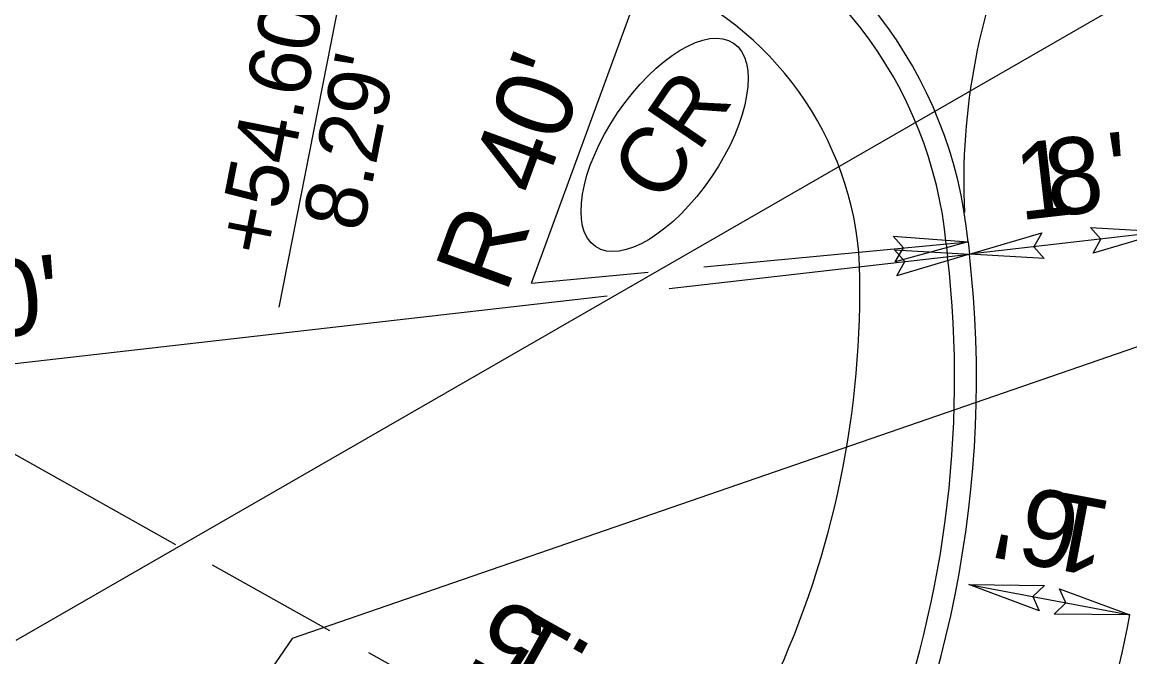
# Model space of a CAD drawing. Extents: x 1975573 to 1977432, y 778300 to 780514.
# Drawn here: x 1976181.7 to 1976308, y 779399.7 to 779472 of the extents above; entities that cross this region are included whole.
import ezdxf

# ---------------------------------------------------------------- set-up
doc = ezdxf.new("R2010")
doc.units = 0
for name, color, linetype in [('Prop Conc 2ft 6in Curb and Gutter', 7, 'Continuous'), ('Prop Conc 4in Sidewalk', 7, 'Continuous'), ('Prop Dimension', 7, 'Continuous'), ('Prop Dimension Text', 7, 'Continuous'), ('Prop EOT', 7, 'Continuous'), ('Prop Horizontal Alignment', 7, 'Continuous'), ('Prop Horizontal Alignment Station Label', 7, 'Continuous'), ('Prop Lane Lines', 7, 'Continuous'), ('Prop Terminator CELL', 7, 'Continuous'), ('Prop WCC CELL', 7, 'Continuous')]:
    doc.layers.add(name, color=color, linetype=linetype)

msp = doc.modelspace()

# ---------------------------------------------------------------- linework, layer by layer
at = {"layer": 'Prop Conc 2ft 6in Curb and Gutter'}
for centre, radius, start, end in [((1976239.78, 779442.27), 47.5, 5.4373, 69.8927), ((1976364.22, 779454.12), 77.5, 185.4373, 186.5318), ((1976165.52, 779431.37), 122.5, 338.3002, 6.5318)]:
    msp.add_arc(centre, radius, start, end, dxfattribs=at)
at = {"layer": 'Prop Conc 4in Sidewalk'}
msp.add_lwpolyline([(1976250.3, 779471.03), (1976250.31, 779471.03)], dxfattribs=at)
for centre, radius, start, end in [((1976239.78, 779442.27), 47.5, 5.4373, 69.8927), ((1976239.78, 779442.27), 47.5, 5.4373, 69.8927), ((1976239.78, 779442.27), 37.5, 5.4373, 69.8927), ((1976239.78, 779442.27), 37.5, 5.4373, 69.8927), ((1976170.99, 779441.37), 106.22, 335.9018, 2.4053), ((1976170.99, 779441.37), 106.22, 335.9018, 2.4053), ((1976364.22, 779454.12), 77.5, 185.4373, 186.5318), ((1976364.22, 779454.12), 77.5, 185.4373, 186.5318), ((1976165.52, 779431.37), 122.5, 338.3002, 6.5318), ((1976165.52, 779431.37), 122.5, 338.3002, 6.5318)]:
    msp.add_arc(centre, radius, start, end, dxfattribs=at)
at = {"layer": 'Prop Dimension'}
msp.add_line((1976211, 779439.54), (1976220.27, 779486.53), dxfattribs=at)
at = {"layer": 'Prop Dimension Text'}
for p, q in [((1976239.78, 779442.27), (1976256.97, 779489.23)), ((1976312.06, 779448.15), (1976289.7, 779445.59)), ((1976259.44, 779444.15), (1976289.56, 779447.01)), ((1976255.46, 779441.67), (1976289.7, 779445.59)), ((1976239.78, 779442.27), (1976253.08, 779443.54)), ((1976165.52, 779431.37), (1976248.42, 779440.86)), ((1976165.52, 779431.37), (1976199.2, 779412.51)), ((1976203.38, 779410.17), (1976216.75, 779402.69)), ((1976289.66, 779407.94), (1976308, 779404.47)), ((1976221.18, 779400.21), (1976274.59, 779370.32))]:
    msp.add_line(p, q, dxfattribs=at)
at = {"layer": 'Prop EOT'}
for centre, radius, start, end in [((1976239.78, 779442.27), 50, 5.4373, 69.8927), ((1976364.22, 779454.12), 75, 185.4373, 186.5318), ((1976165.52, 779431.37), 125, 330.7648, 6.5318)]:
    msp.add_arc(centre, radius, start, end, dxfattribs=at)
at = {"layer": 'Prop Horizontal Alignment'}
msp.add_arc((1978303.2, 778082.63), 2375, 135.73946, 152.1381, dxfattribs=at)
at = {"layer": 'Prop Horizontal Alignment Station Label'}
for p, q in [((1976321.01, 779482.16), (1976180.99, 779401.56)), ((1976362.45, 779453.51), (1976212.49, 779401.79)), ((1976212.49, 779401.79), (1976125.99, 779275.55))]:
    msp.add_line(p, q, dxfattribs=at)
at = {"layer": 'Prop Lane Lines'}
for centre, radius, start, end in [((1976364.16, 779453.7), 75.1, 155.8173, 182.5752), ((1976165.52, 779431.37), 145, 330.7648, 349.3113)]:
    msp.add_arc(centre, radius, start, end, dxfattribs=at)
at = {"layer": 'Prop Terminator CELL'}
for points in [[(1976303.51, 779448.63), (1976312.06, 779448.15), (1976303.8, 779445.69), (1976304.7, 779447.3)], [(1976281.02, 779447.66), (1976289.56, 779447.01), (1976281.25, 779444.71), (1976282.18, 779446.31)], [(1976298.25, 779445.1), (1976289.7, 779445.59), (1976297.96, 779448.04), (1976297.06, 779446.43)], [(1976281.16, 779446.07), (1976289.7, 779445.59), (1976281.45, 779443.13), (1976282.35, 779444.74)], [(1976297.68, 779404.94), (1976289.66, 779407.94), (1976298.27, 779407.84), (1976296.94, 779406.56)], [(1976299.98, 779407.47), (1976308, 779404.47), (1976299.39, 779404.57), (1976300.72, 779405.85)]]:
    msp.add_lwpolyline(points, close=True, dxfattribs=at)
at = {"layer": 'Prop WCC CELL'}
msp.add_ellipse((1976254.95, 779458.05), major_axis=(7.87, 11.6), ratio=0.462467, dxfattribs=at)

# ---------------------------------------------------------------- texts
at = {"layer": 'Prop Dimension'}
for s, p in [("+54.60'", (1976210.46, 779445.08)), ("8.29'", (1976220.51, 779447.96))]:
    msp.add_text(s, height=7, rotation=78.8445, dxfattribs=at).set_placement(p)
at = {"layer": 'Prop Dimension Text'}
for s, rotation, p in [("R 40'", 69.8927, (1976236.86, 779440.96)), ('1', 6.5318, (1976295.44, 779449.44)), ('8', 6.5318, (1976298.86, 779449.83)), ("'", 6.5318, (1976306.12, 779450.66)), ("R 100'", 6.5318, (1976153.31, 779433.13)), ('6', 169.3113, (1976302.83, 779417.97)), ('1', 169.3113, (1976306.21, 779417.33)), ("'", 169.3113, (1976295.93, 779419.27)), ('5', 150.7648, (1976242.08, 779403.56)), ('1', 150.7648, (1976245.08, 779401.88)), ('.', 150.7648, (1976247.13, 779400.73))]:
    msp.add_text(s, height=8.75, rotation=rotation, dxfattribs=at).set_placement(p)
at = {"layer": 'Prop WCC CELL'}
msp.add_text('CR', height=7.5, rotation=55.8441, dxfattribs=at).set_placement((1976254.7, 779451.1))

doc.saveas('drawing.dxf')
